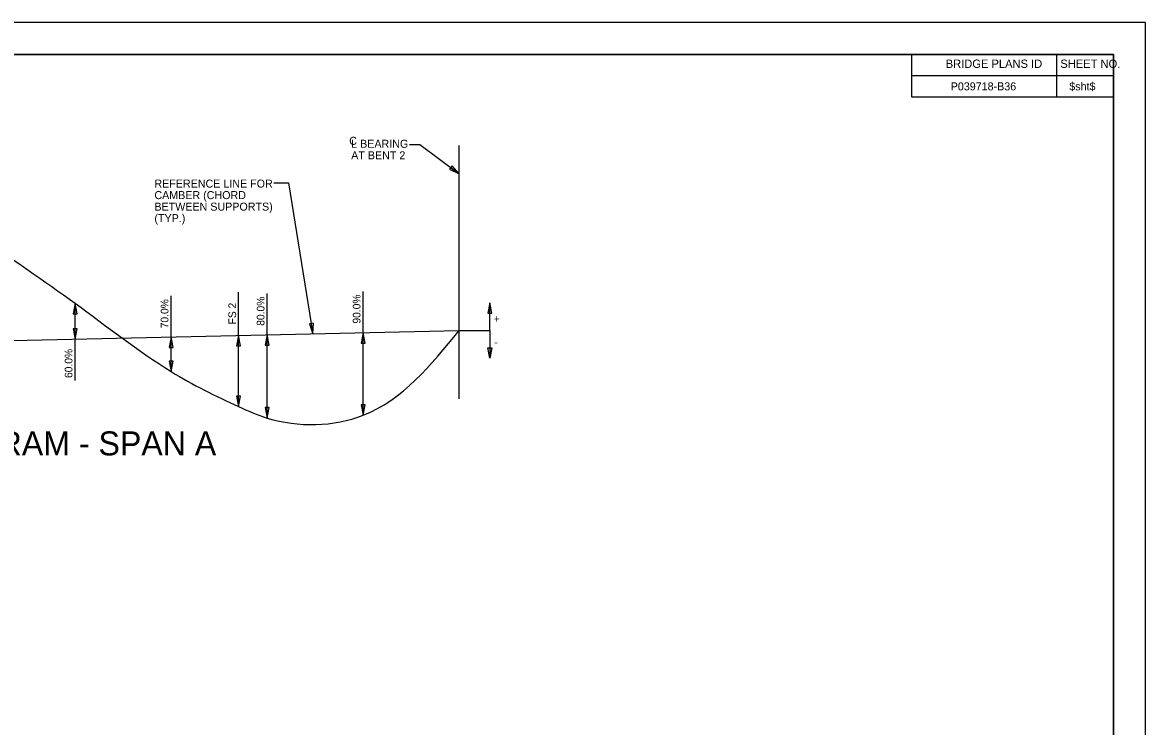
# Model space of a CAD drawing. Extents: x -125.5 to -89.4, y -5.1 to 16.9.
# Drawn here: x -107.08 to -89.53, y 5.93 to 16.93 of the extents above; entities that cross this region are included whole.
import ezdxf

# ---------------------------------------------------------------- set-up
doc = ezdxf.new("R2010")
doc.units = 0
for name, color, linetype in [('BR_AUTO DIMENSION', 7, 'Continuous'), ('BR_BORDER LINES', 7, 'Continuous'), ('BR_CENTER LINES', 7, 'Continuous'), ('BR_TABLE LINES', 7, 'Continuous'), ('BR_TEXT', 7, 'Continuous'), ('Level 31', 7, 'Continuous')]:
    doc.layers.add(name, color=color, linetype=linetype)

msp = doc.modelspace()

# ---------------------------------------------------------------- linework, layer by layer
at = {"layer": 'BR_AUTO DIMENSION'}
for p, q in [((-101.03, 15.029), (-100.87, 15.029)), ((-100.87, 15.029), (-100.257, 14.57)), ((-103.149, 14.427), (-102.919, 14.427)), ((-102.919, 14.427), (-102.54, 12.07)), ((-100.257, 12.121), (-99.777, 12.121))]:
    msp.add_line(p, q, dxfattribs=at)
for points in [[(-100.405, 14.644), (-100.257, 14.57), (-100.367, 14.694)], [(-106.222, 12.384), (-106.253, 12.546), (-106.285, 12.384)], [(-99.746, 12.392), (-99.777, 12.554), (-99.809, 12.392)], [(-106.285, 12.149), (-106.253, 11.986), (-106.222, 12.149)], [(-102.593, 12.227), (-102.54, 12.07), (-102.531, 12.235)], [(-104.722, 11.857), (-104.753, 12.02), (-104.785, 11.857)], [(-103.672, 11.881), (-103.703, 12.043), (-103.735, 11.881)], [(-103.222, 11.891), (-103.253, 12.054), (-103.285, 11.891)], [(-101.722, 11.925), (-101.753, 12.087), (-101.785, 11.925)], [(-99.746, 11.85), (-99.777, 11.688), (-99.809, 11.85)], [(-104.785, 11.642), (-104.753, 11.48), (-104.722, 11.642)], [(-103.735, 11.095), (-103.703, 10.933), (-103.672, 11.095)], [(-103.285, 10.916), (-103.253, 10.754), (-103.222, 10.916)], [(-101.785, 10.96), (-101.753, 10.797), (-101.722, 10.96)]]:
    msp.add_lwpolyline(points, close=True, dxfattribs=at)
at = {"layer": 'BR_BORDER LINES'}
for p, q in [((-90.033, 16.434), (-123.699, 16.434)), ((-93.186, 15.767), (-93.186, 16.434)), ((-90.919, 15.767), (-90.919, 16.434)), ((-90.033, -4.566), (-90.033, 16.434)), ((-93.186, 16.104), (-90.033, 16.104)), ((-90.919, 16.104), (-90.033, 16.104)), ((-90.033, 15.767), (-93.186, 15.767))]:
    msp.add_line(p, q, dxfattribs=at)
at = {"layer": 'BR_CENTER LINES'}
msp.add_line((-100.257, 11.055), (-100.257, 15.009), dxfattribs=at)
at = {"layer": 'BR_TABLE LINES'}
for p, q in [((-104.753, 11.48), (-104.753, 12.664)), ((-103.703, 10.933), (-103.703, 12.718)), ((-103.253, 10.754), (-103.253, 12.698)), ((-101.753, 10.797), (-101.753, 12.732)), ((-106.253, 11.342), (-106.253, 12.546)), ((-99.777, 12.121), (-99.777, 12.554)), ((-115.253, 11.784), (-100.257, 12.121)), ((-99.777, 12.121), (-99.777, 11.688))]:
    msp.add_line(p, q, dxfattribs=at)
msp.add_lwpolyline([(-123.699, 16.434), (-90.033, 16.434), (-90.033, -4.566), (-123.699, -4.566)], close=True, dxfattribs=at)
msp.add_spline([(-115.253, 11.784), (-113.783, 12.329), (-112.253, 12.991), (-111.503, 13.388), (-110.753, 13.775), (-109.253, 14.389), (-107.753, 13.612), (-106.253, 12.546), (-104.753, 11.48), (-103.702, 10.932), (-103.253, 10.754), (-101.753, 10.797), (-100.257, 12.121)], degree=3, dxfattribs=at)
at = {"layer": 'Level 31'}
msp.add_lwpolyline([(-125.533, -5.066), (-89.533, -5.066), (-89.533, 16.934), (-125.533, 16.934)], close=True, dxfattribs=at)

# ---------------------------------------------------------------- texts
at = {"layer": 'BR_AUTO DIMENSION'}
for s, p in [('C', (-101.973, 15.022)), ('L BEARING', (-101.942, 14.976)), ('AT BENT 2', (-101.942, 14.796)), ('REFERENCE LINE FOR', (-105.016, 14.354)), ('CAMBER (CHORD', (-105.016, 14.174)), ('BETWEEN SUPPORTS)', (-105.016, 13.994)), ('(TYP.)', (-105.016, 13.814))]:
    msp.add_text(s, height=0.125, dxfattribs=at).set_placement(p)
at = {"layer": 'BR_TEXT'}
for s, height, p in [('BRIDGE PLANS ID', 0.13, (-92.654, 16.224)), ('SHEET NO.', 0.13, (-90.864, 16.224)), ('P039718-B36', 0.125, (-92.576, 15.873)), ('$sht$', 0.125, (-90.724, 15.873)), ('-', 0.12, (-99.706, 11.88)), ('CAMBER DIAGRAM - SPAN A', 0.375, (-110.96, 10.17))]:
    msp.add_text(s, height=height, dxfattribs=at).set_placement(p)
for s, rotation, p in [('80.0%', 90, (-103.297, 12.195)), ('90.0%', 90, (-101.797, 12.229)), ('70.0%', 90, (-104.797, 12.156)), ('FS 2', 90, (-103.74, 12.216)), ('+', 360, (-99.716, 12.242)), ('60.0%', 90, (-106.297, 11.379))]:
    msp.add_text(s, height=0.12, rotation=rotation, dxfattribs=at).set_placement(p)

doc.saveas('drawing.dxf')
